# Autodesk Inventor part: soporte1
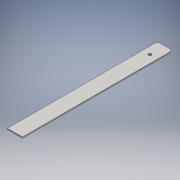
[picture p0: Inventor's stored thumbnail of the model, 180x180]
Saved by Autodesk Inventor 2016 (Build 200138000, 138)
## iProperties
Created: 2016-06
Part Number: soporte1
Material: Genérico
Document SubType Name: Modeling
Designer: adm
Density: 1 g/cm^3
Appearance: Valor por defecto
Author: adm
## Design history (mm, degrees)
sketch "Boceto1"
  geometry: L1 (-25, -250)-(25, -250); L2 (25, -250)-(25, 250); L3 (25, 250)-(-25, 250); L4 (-25, 250)-(-25, -250); L5 (-25, -250)-(25, 250); L6 (25, -250)-(-25, 250); C1 r 5 at (0, 200); 2 further points
  constraints: 12 end point, 2 midpoint, 2 parallel, 1 centre point, 1 coincident, 1 horizontal, 1 perpendicular
  dimensions: "d0" = 50 distance of L3.end L2.end; "d1" = 500 distance of L2.end L1.end; "d2" = 50 distance from line of point (0, 200) L3; "d3" = 10 diameter of C1
extrude "Extrusión1" new body sketch "Boceto1" distance "d4" = 4; taper "d5" = 0 deg
fillet "Empalme1" dims "d6" = 10
node "Sólido1"
